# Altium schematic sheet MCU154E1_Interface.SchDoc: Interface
size A4; Date: Not shown in title block; ApprovedBy: Not shown in title block; CheckedBy: Not shown in title block; Author: Not shown in title block; CompanyName: Not shown in title block; DrawnBy: Hely Zhang; Engineer: Not shown in title block; Organization: Not shown in title block; Address1: Not shown in title block; Address2: Not shown in title block; Address3: Not shown in title block; Address4: Not shown in title block; DocumentNumber: 1; Revision: Use project parameter SCH_Rev; SheetNumber: 4; SheetTotal: 5; PageSetup: Record=PageOptions¦CenterHorizontal=True¦CenterVertical=True¦PrintScale=0.93¦XCorrection=1.00¦YCorrection=1.00¦PrintKind=0¦BorderSize=5000000¦LeftOffset=0¦BottomOffset=0¦Orientation=2¦PaperLength=1000¦PaperWidth=1000¦Scale=100¦PaperSource=15¦PrintQuality=600¦MediaType=1¦DitherType=10¦PaperKind=Letter¦PrintScaleMode=1
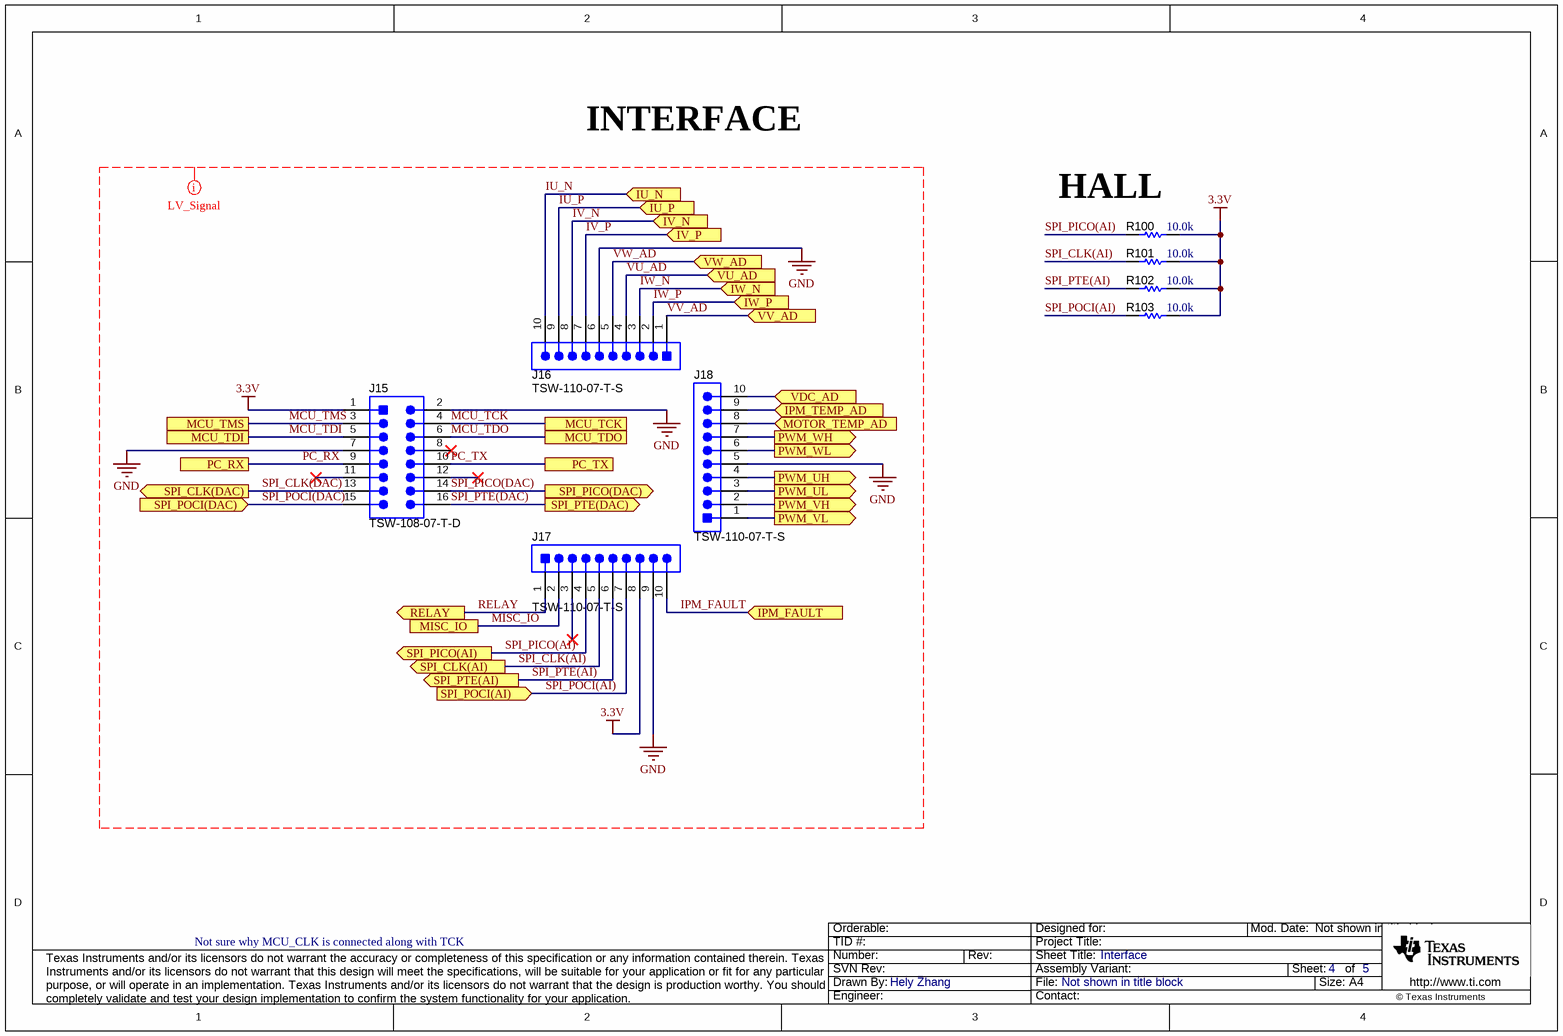
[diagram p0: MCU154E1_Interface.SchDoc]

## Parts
J15  TSW-108-07-T-D  [FP-TSW-108-07-T-D_HDR16-MFG]
J16  TSW-110-07-T-S  [FP-TSW-110-07-T-S_HDR10-MFG]
J17  TSW-110-07-T-S  [FP-TSW-110-07-T-S_HDR10-MFG]
J18  TSW-110-07-T-S  [FP-TSW-110-07-T-S_HDR10-MFG]
R100  ValueDisplayed: 10.0k  [0603]  (hidden comment: RC0603FR-0710KL)
R101  ValueDisplayed: 10.0k  [0603]  (hidden comment: RC0603FR-0710KL)
R102  ValueDisplayed: 10.0k  [0603]  (hidden comment: RC0603FR-0710KL)
R103  ValueDisplayed: 10.0k  [0603]  (hidden comment: RC0603FR-0710KL)

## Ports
IPM_FAULT (in), IPM_TEMP_AD (in), IU_N (in), IU_P (in), IV_N (in), IV_P (in), IW_N (in), IW_P (in), MCU_TCK, MCU_TDI, MCU_TDO, MCU_TMS, MISC_IO, MOTOR_TEMP_AD (in), PC_RX, PC_TX, PWM_UH (out), PWM_UL (out), PWM_VH (out), PWM_VL (out), PWM_WH (out), PWM_WL (out), RELAY (out), SPI_CLK(AI) (out), SPI_CLK(DAC) (out), SPI_PICO(AI) (out), SPI_PICO(DAC) (out), SPI_POCI(AI) (in), SPI_POCI(DAC) (in), SPI_PTE(AI) (out), SPI_PTE(DAC) (out), VDC_AD (in), VU_AD (in), VV_AD (in), VW_AD (in)

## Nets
3.3V: J15.1 J17.8 R100.1 R101.1 R102.1 R103.1
GND: J15.2 J15.7 J16.6 J17.9 J18.5
IPM_FAULT: J17.10 ; port IPM_FAULT
IPM_TEMP_AD: J18.9 ; port IPM_TEMP_AD
IU_N: J16.10 ; port IU_N
IU_P: J16.9 ; port IU_P
IV_N: J16.8 ; port IV_N
IV_P: J16.7 ; port IV_P
IW_N: J16.3 ; port IW_N
IW_P: J16.2 ; port IW_P
MCU_TCK: J15.4 ; port MCU_TCK
MCU_TDI: J15.5 ; port MCU_TDI
MCU_TDO: J15.6 ; port MCU_TDO
MCU_TMS: J15.3 ; port MCU_TMS
MISC_IO: J17.2 ; port MISC_IO
MOTOR_TEMP_AD: J18.8 ; port MOTOR_TEMP_AD
PC_RX: J15.9 ; port PC_RX
PC_TX: J15.10 ; port PC_TX
PWM_UH: J18.4 ; port PWM_UH
PWM_UL: J18.3 ; port PWM_UL
PWM_VH: J18.2 ; port PWM_VH
PWM_VL: J18.1 ; port PWM_VL
PWM_WH: J18.7 ; port PWM_WH
PWM_WL: J18.6 ; port PWM_WL
RELAY: J17.1 ; port RELAY
SPI_CLK(AI): J17.5 R101.2 ; port SPI_CLK(AI)
SPI_CLK(DAC): J15.13 ; port SPI_CLK(DAC)
SPI_PICO(AI): J17.4 R100.2 ; port SPI_PICO(AI)
SPI_PICO(DAC): J15.14 ; port SPI_PICO(DAC)
SPI_POCI(AI): J17.7 R103.2 ; port SPI_POCI(AI)
SPI_POCI(DAC): J15.15 ; port SPI_POCI(DAC)
SPI_PTE(AI): J17.6 R102.2 ; port SPI_PTE(AI)
SPI_PTE(DAC): J15.16 ; port SPI_PTE(DAC)
VDC_AD: J18.10 ; port VDC_AD
VU_AD: J16.4 ; port VU_AD
VV_AD: J16.1 ; port VV_AD
VW_AD: J16.5 ; port VW_AD

Not connected (* = marked no-connect by the designer): J15 8* 11* 12*; J17 3*

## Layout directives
net class LV_Signal: 3.3V, GND, IPM_FAULT, IU_N, IU_P, IV_N, IV_P, IW_N, IW_P, MCU_TCK, MCU_TDI, MCU_TDO, MCU_TMS, MISC_IO, PC_RX, PC_TX, RELAY, SPI_CLK(AI), SPI_CLK(DAC), SPI_PICO(AI), SPI_PICO(DAC), SPI_POCI(AI), SPI_POCI(DAC), SPI_PTE(AI), SPI_PTE(DAC), VU_AD, VV_AD, VW_AD

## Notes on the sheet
- INTERFACE
- (near R100) HALL
- Not sure why MCU_CLK is connected along with TCK

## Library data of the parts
J15 = CMP-0123024-2: Connector Header Through Hole 16 position 0.100" (2.54mm); Manufacturer: Samtec; ContactFinish: Tin,Nickel; Row_Count: 2; AEC Qualified: No; Category 0836C53C3D42D3F1: Connectors; Category 75Fab8F04590Ae3D: Connectors and Adapters; Category A3C16Ecb93907806: Uncategorized; Category E7012A0Bd22E3Cc6: Headers & Receptacles; Conn Gender: Male; Conn Orientation: Vertical; SizeZ_mm: 8.71mm
J16-J18 = CMP-0123044-2: Conn Unshrouded Header HDR 10 POS 2.54mm Solder ST Top Entry Thru-Hole Bag; Manufacturer: Samtec; ContactFinish: Tin,Nickel; Row_Count: 1; AEC Qualified: No; Category 0836C53C3D42D3F1: Connectors; Category 75Fab8F04590Ae3D: Connectors and Adapters; Category A3C16Ecb93907806: Uncategorized; Category E7012A0Bd22E3Cc6: Headers & Receptacles; Conn Gender: Male; Conn Orientation: Vertical; SizeZ_mm: 8.71mm
R100-R103 = CMP-0022746-5: RES, 10.0 k, 1%, 0.1 W, 0603; Manufacturer: Yageo; Power_W: 100mW; TempCo: 100 ppm/C; Value_Code: 10k0; Value: 10.0k; EIA_Code: E96; Res_ohm: 10k; SizeX_mm: 1.6; SizeY_mm: 0.8; SizeZ_mm: 1; Value2: 0.1W; SizeArea_mm2: 1.28; AEC Qualified: N; VDC_V: 75V; AEC Category: Q200; SizeAreaWB_mm2: 4.68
